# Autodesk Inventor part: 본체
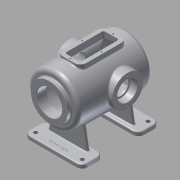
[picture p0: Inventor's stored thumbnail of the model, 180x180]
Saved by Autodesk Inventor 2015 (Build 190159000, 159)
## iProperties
Created: 2016-02
Part Number: 본체
Material: 알루미늄 6061
Document SubType Name: Modeling
Designer: mduedu
Density: 2.71 g/cm^3
Appearance: 알루미늄 - 평지
Mass: 3305.63 g
Surface Area: 2487.05 cm^2
Volume: 1219.79 cm^3
Author: mduedu
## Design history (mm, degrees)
sketch "스케치2"
  geometry: L1 (0, 100)-(0, -100); L2 (65, -87.083)-(65, 100); L3 (65, 100)-(0, 100); A1 r 170 centre (0, 70) between (0, -100) and (65, -87.083); 2 further points
  constraints: 6 end point, 2 point on circle, 1 centre point, 1 coincident, 1 horizontal, 1 midpoint, 1 parallel, 1 point on line, 1 vertical
  dimensions: "d3" = 200 distance of L1.start L1.end; "d5" = 130 diameter of L2 L1; "d6" = 170 radius of A1
revolve "회전1" sketch "스케치2" stored, may be unused: angle "d7" = 90 deg
sketch "스케치3"
  geometry: C1 r 47.5 at (0, 0); 1 further point
  constraints: 1 centre point, 1 coincident
  dimensions: "d8" = 95 diameter of C1
extrude "돌출2" join sketch "스케치3" distance "d10" = 10; taper "d11" = 0 deg
sketch "스케치5"
  geometry: L1 (47.5, 110)-(47.5, 100) reference; L2 (47.5, 100)-(65, 100) reference; L3 (65, 100)-(65, -87.083) reference; L4 (-65, -87.083)-(-65, 100) reference; L5 (-65, 100)-(-47.5, 100) reference; L6 (-47.5, 100)-(-47.5, 110) reference; L7 (-47.5, 110)-(47.5, 110) reference; L8 (55, 85)-(55, -80.25); L9 (0, 85)-(55, 85); L10 (0, 85)-(0, -90); A1 r 170 centre (0, 70) between (-65, -87.083) and (0, -100) reference; A2 r 170 centre (0, 70) between (0, -100) and (65, -87.083) reference; A3 r 160 centre (0, 70) between (0, -90) and (55, -80.25); 1 further point
  constraints: 6 end point, 2 point on circle, 1 centre point, 1 parallel, 1 perpendicular, 1 point on line, 1 vertical
  dimensions: "d13" = 10 distance between parallel lines of L3 L8; "d14" = 10 radial gap between concentric circles of A3 A1; "d15" = 15 distance between parallel lines of L9 L2
revolve "회전2" sketch "스케치5" stored, may be unused: angle "d16" = 90 deg
hole "구멍1" diameter "d19" = 65; stored, may be unused: countersink angle "d23" = 90 deg, drill point angle "d25" = 118 deg; dims "d17" = 10, "d18" = 10, "d20" = 6, "d21" = 4, "d22" = 2, "d24" = 8
node "작업 평면1"
sketch "스케치6"
  geometry: L1 (47.5, 110)-(-47.5, 110) reference; C1 r 40 at (0, -17); 1 further point
  constraints: 1 centre point, 1 vertical alignment
  dimensions: "d27" = 80 diameter of C1; "d29" = 127 distance from line of C1.centre L1
extrude "돌출3" join sketch "스케치6" stored distance "d30" = 10; taper "d31" = 0 deg
hole "구멍2" diameter "d34" = 42; stored, may be unused: countersink angle "d38" = 90 deg, drill point angle "d40" = 118 deg; dims "d32" = 10, "d33" = 10, "d35" = 6, "d36" = 52, "d37" = 18, "d39" = 8
sketch "스케치7" dims "d41" = 65
  geometry: C1 r 40 at (0, 0) reference; 3 further points
  constraints: 2 vertical alignment, 1 coincident, 2 other
hole "구멍3" sketch "스케치7" at (0, 32.5) diameter "d43" = 3.242; stored, may be unused: countersink angle "d47" = 90 deg, drill point angle "d49" = 118 deg; dims "d44" = 11, "d45" = 13, "d46" = 18, "d48" = 13
sketch "스케치8" dims "d53" = 80
  geometry: 3 further points
  constraints: 2 vertical alignment, 1 coincident, 2 other
hole "구멍4" sketch "스케치8" at (0, 40) diameter "d56" = 3.242; stored, may be unused: countersink angle "d60" = 90 deg, drill point angle "d62" = 118 deg; dims "d57" = 11, "d58" = 13, "d59" = 18, "d61" = 13
fillet "모깎기1" dims "d66" = 10
fillet "모깎기2" dims "d67" = 3
fillet "모깎기3" dims "d68" = 0.3
chamfer "모따기1" distance "d69" = 1; stored, may be unused: second distance "d70" = 2, angle "d71" = 45 deg
node "작업 평면2"
sketch "스케치9"
  geometry: L1 (75, 100)-(-75, 100); L2 (-75, 100)-(-75, -100); L3 (-75, -100)-(75, -100); L4 (75, -100)-(75, 100); 1 further point
  constraints: 8 end point, 2 parallel, 1 horizontal, 1 perpendicular
  dimensions: "d73" = 200 distance of L3.end L1.start; "d75" = 150 distance of L2.end L3.end; "d76" = 100 distance from line of L1 point (0, 0); "d77" = 75 distance from line of L4 point (0, 0)
extrude "돌출4" join sketch "스케치9" distance "d78" = 10; taper "d79" = 0 deg
sketch "스케치10"
  geometry: L1 (-75, -100)-(75, -100) reference; L2 (75, 100)-(-75, 100) reference; L3 (0, -100)-(0, 100); L4 (-75, 100)-(-75, -100) reference; L5 (75, -100)-(75, 100) reference; L6 (-75, 0)-(75, 0); L7 (-50, -63)-(50, -63); L8 (50, -63)-(50, -55); L9 (50, -55)-(-50, -55); L10 (-50, -55)-(-50, -63); L11 (-50, 63)-(50, 63); L12 (50, 63)-(50, 55); L13 (50, 55)-(-50, 55); L14 (-50, 55)-(-50, 63); 1 further point
  constraints: 20 end point, 4 midpoint, 4 symmetric about line, 2 parallel, 1 horizontal, 1 perpendicular, 1 other
  dimensions: "d80" = 8 distance of L9.end L7.start; "d82" = 100 distance of L7.start L7.end; "d83" = 55 distance between parallel lines of L9 L6
extrude "돌출5" join sketch "스케치10" stored distance "d84" = 10; taper "d85" = 0 deg
feature "면 기울기1" dims angle "d86" = 10 deg
sketch "스케치11"
  geometry: L1 (-110, 55)-(-51.482, 55) reference; L2 (-110, -55)-(-51.482, -55) reference; L3 (-95, 55)-(-95, -55); L4 (-65, 90)-(-65, -80.25) reference; 1 further point
  constraints: 2 end point, 2 point on line, 1 perpendicular
  dimensions: "d87" = 30 distance between parallel lines of L3 L4
feature "리브1" sketch "스케치11" dims "d88" = 1, "d89" = 8, "d90" = 0, "d91" = 0, "d92" = 1, "d93" = 1
sketch "스케치12"
  geometry: L1 (-110, 55)-(-51.482, 55) reference; L2 (-110, -55)-(-51.482, -55) reference; L3 (-110, 100)-(-110, -100) reference; L4 (-120, 152)-(-120, -142) reference; L5 (-110, 45)-(-120, 45); L6 (-120, 45)-(-120, -45); L7 (-120, -45)-(-110, -45); L8 (-110, -45)-(-110, 45); 1 further point
  constraints: 8 end point, 2 parallel, 2 point on line, 1 horizontal, 1 perpendicular
  dimensions: "d94" = 10 distance between parallel lines of L7 L2; "d95" = 10 distance between parallel lines of L1 L5
extrude "돌출6" cut sketch "스케치12" stored distance "d96" = 10; taper "d97" = 0 deg
fillet "모깎기4" dims "d98" = 15
sketch "스케치13"
  geometry: C1 r 5 at (-60, -85); C2 r 5 at (60, -85); C3 r 5 at (60, 85); C4 r 5 at (-60, 85); A1 r 15 centre (-60, -85) between (-75, -85) and (-60, -100) reference; A2 r 15 centre (60, -85) between (60, -100) and (75, -85) reference; A3 r 15 centre (60, 85) between (75, 85) and (60, 100) reference; A4 r 15 centre (-60, 85) between (-60, 100) and (-75, 85) reference; 1 further point
  constraints: 4 centre point, 4 coincident, 3 equal radius
  dimensions: "d99" = 10 diameter of C1
extrude "돌출7" cut sketch "스케치13" stored distance "d101" = 10; taper "d102" = 0 deg
fillet "모깎기5" dims "d103" = 3, "d104" = 3
fillet "모깎기6" dims "d105" = 3
sketch "스케치14"
  geometry: L1 (-60, -100)-(60, -100) reference; 2 further points
  constraints: 1 vertical alignment, 1 other
  dimensions: "d106" = 15 distance from line of point (0, -85) L1
feature "엠보싱1" sketch "스케치14" dims "d3" = 200, "d5" = 130, "d6" = 170, "d14" = 10, "d107" = 0.5, "d108" = 0
node "작업 평면3"
sketch "스케치15"
  geometry: L1 (-30, 60)-(30, 60); L2 (30, 60)-(30, -60); L3 (30, -60)-(-30, -60); L4 (-30, -60)-(-30, 60); 2 further points
  constraints: 8 end point, 2 parallel, 1 horizontal, 1 midpoint, 1 perpendicular, 1 vertical alignment
  dimensions: "d110" = 60 distance of L2.end L3.end; "d112" = 60 distance from line of L3 point (0, 0); "d113" = 120 distance of L1.end L2.end
extrude "돌출8" join sketch "스케치15" stored distance "d114" = 10; taper "d115" = 0 deg
fillet "모깎기7" dims "d116" = 15
sketch "스케치16"
  geometry: L1 (-30, -45)-(-30, 45) reference; L2 (-15, 60)-(15, 60) reference; L3 (30, 45)-(30, -45) reference; L4 (15, -60)-(-15, -60) reference; L5 (15, 50)-(-15, 50); L6 (-20, 45)-(-20, -45); L7 (-15, -50)-(15, -50); L8 (20, -45)-(20, 45); A1 r 15 centre (-15, -45) between (-30, -45) and (-15, -60) reference; A2 r 15 centre (-15, 45) between (-15, 60) and (-30, 45) reference; A3 r 15 centre (15, 45) between (30, 45) and (15, 60) reference; A4 r 15 centre (15, -45) between (15, -60) and (30, -45) reference; A5 r 5 centre (-15, 45) between (-15, 50) and (-20, 45); A6 r 5 centre (-15, -45) between (-20, -45) and (-15, -50); A7 r 5 centre (15, -45) between (15, -50) and (20, -45); A8 r 5 centre (15, 45) between (20, 45) and (15, 50); 1 further point
  constraints: 8 end point, 8 point on circle, 4 centre point, 7 other
  dimensions: "d117" = 10 distance between parallel lines of L6 L1
extrude "돌출9" cut sketch "스케치16" stored distance "d118" = 10; taper "d119" = 0 deg
fillet "모깎기8" dims "d120" = 3
sketch "스케치17"
  geometry: L1 (-30, -45)-(-30, 45) reference; L2 (-15, 60)-(15, 60) reference; L3 (30, 45)-(30, -45) reference; L4 (15, -60)-(-15, -60) reference; L5 (20, -45)-(20, 45) reference; L6 (15, 50)-(-15, 50) reference; L7 (-20, 45)-(-20, -45) reference; L8 (-15, -50)-(15, -50) reference; L9 (15, 55)-(-15, 55); L10 (-25, 45)-(-25, -45); L11 (-15, -55)-(15, -55); L12 (25, -45)-(25, 45); A1 r 15 centre (-15, 45) between (-15, 60) and (-30, 45) reference; A2 r 15 centre (15, 45) between (30, 45) and (15, 60) reference; A3 r 15 centre (15, -45) between (15, -60) and (30, -45) reference; A4 r 15 centre (-15, -45) between (-30, -45) and (-15, -60) reference; A5 r 5 centre (15, -45) between (15, -50) and (20, -45) reference; A6 r 5 centre (15, 45) between (20, 45) and (15, 50) reference; A7 r 5 centre (-15, 45) between (-15, 50) and (-20, 45) reference; A8 r 5 centre (-15, -45) between (-20, -45) and (-15, -50) reference; A9 r 10 centre (-15, 45) between (-15, 55) and (-25, 45); A10 r 10 centre (-15, -45) between (-25, -45) and (-15, -55); A11 r 10 centre (15, -45) between (15, -55) and (25, -45); A12 r 10 centre (15, 45) between (25, 45) and (15, 55); 5 further points
  constraints: 8 end point, 8 point on circle, 4 centre point, 4 midpoint, 7 other
  dimensions: "d121" = 5 distance between parallel lines of L10 L1
hole "구멍5" sketch "스케치17" at (0, 55), (25, 0), (0, -55), (-25, 0) diameter "d122" = 3.242; stored, may be unused: countersink angle "d126" = 90 deg, drill point angle "d128" = 118 deg; dims "d123" = 9, "d124" = 13, "d125" = 18, "d127" = 11
fillet "모깎기9" dims "d129" = 3
node "솔리드2"
pattern_circular "원형 패턴1" dims angle "d51" = 360 deg
mirror "대칭1"
pattern_circular "원형 패턴2" dims angle "d64" = 360 deg
node "절단 모서리 투영1"
node "절단 모서리 투영2"
node "절단 모서리 투영3"
other parameters: "d26" = 75
